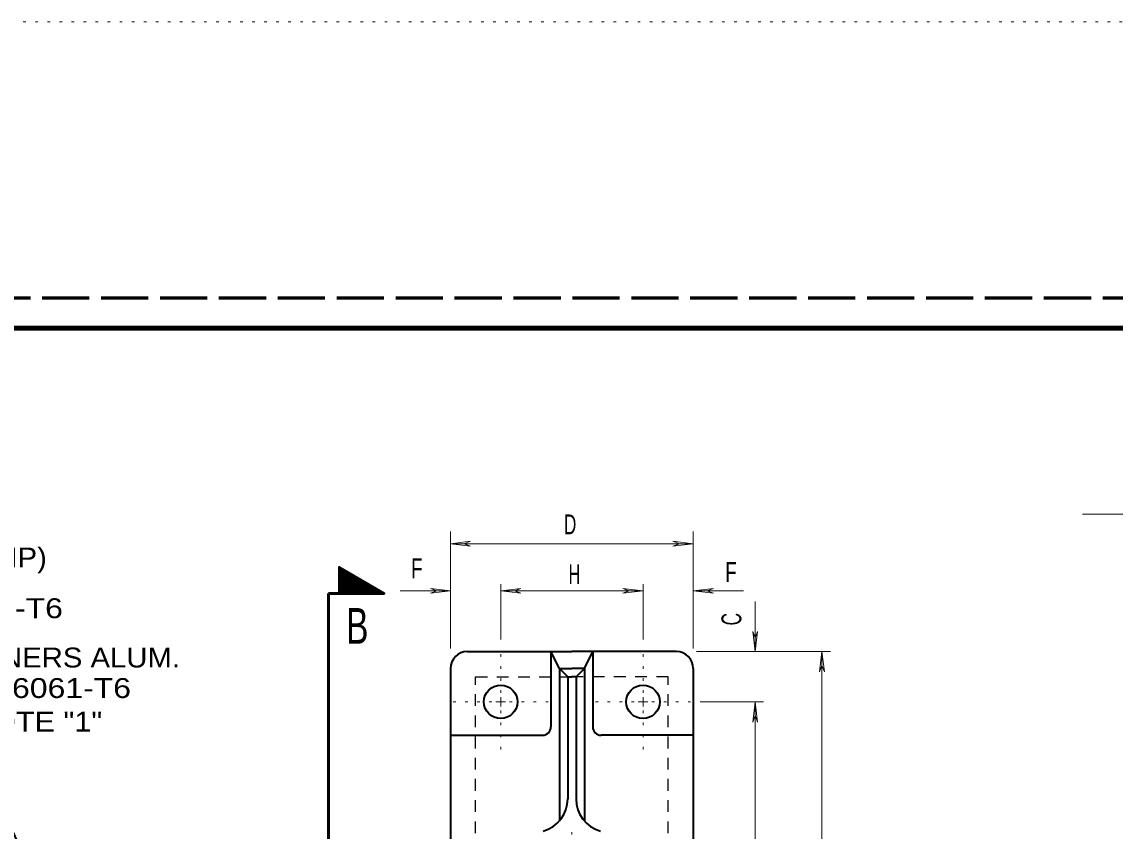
# Model space of a CAD drawing. Extents: x 312583 to 312854, y 144419 to 144597.
# Drawn here: x 312666.93 to 312708.67, y 144565.87 to 144596.78 of the extents above; entities that cross this region are included whole.
import ezdxf
from ezdxf.enums import TextEntityAlignment as Align

# ---------------------------------------------------------------- set-up
doc = ezdxf.new("R2010")
doc.units = 0
doc.header["$LTSCALE"] = 0.3
for name, pattern in [('DOTTED', [1.5, 0.3, -1.2]), ('LONG_DASH_SHORT_DASH', [9.9, 6, -1.2, 1.5, -1.2]), ('LONG_DASHED', [7.5, 6, -1.5]), ('SHORT_DASHED', [2.7, 1.5, -1.2])]:
    doc.linetypes.add(name, pattern=pattern)
for name, color, linetype, lineweight in [('1', 7, 'Continuous', 35), ('2', 7, 'Continuous', 13), ('62', 7, 'DOTTED', 13), ('63', 7, 'LONG_DASHED', 60)]:
    doc.layers.add(name, color=color, linetype=linetype, lineweight=lineweight)

msp = doc.modelspace()

# ---------------------------------------------------------------- linework, layer by layer
at = {"layer": '1', "linetype": 'LONG_DASH_SHORT_DASH', "lineweight": 13}
msp.add_line((312707.4292, 144577.9729), (312828.5012, 144577.9729), dxfattribs=at)
at = {"layer": '1'}
for p, q in [((312679.0537, 144575.9106), (312679.069, 144575.9259)), ((312679.0537, 144575.8723), (312679.0843, 144575.9183)), ((312679.0537, 144575.8263), (312679.0997, 144575.9029)), ((312679.0537, 144575.7803), (312679.1227, 144575.8953)), ((312679.0537, 144575.7343), (312679.138, 144575.8876)), ((312679.0537, 144575.7036), (312679.1533, 144575.8723)), ((312679.0537, 144575.6576), (312679.1763, 144575.8646)), ((312679.0537, 144575.6116), (312679.1917, 144575.8493)), ((312679.0537, 144575.5733), (312679.207, 144575.8416)), ((312679.0537, 144575.5349), (312679.2377, 144575.8339)), ((312679.0537, 144575.4813), (312679.253, 144575.8263)), ((312679.0537, 144575.4429), (312679.2683, 144575.8109)), ((312679.0537, 144575.4046), (312679.2913, 144575.8033)), ((312679.0537, 144575.3509), (312679.3067, 144575.7879)), ((312679.0537, 144575.3126), (312679.322, 144575.7803)), ((312679.0537, 144575.2743), (312679.3373, 144575.7726)), ((312679.0537, 144575.2283), (312679.3603, 144575.7573)), ((312679.0537, 144575.1823), (312679.3757, 144575.7496)), ((312679.0537, 144575.1439), (312679.391, 144575.7343)), ((312679.0537, 144575.1056), (312679.414, 144575.7189)), ((312679.0537, 144575.0519), (312679.437, 144575.7189)), ((312679.0537, 144575.0213), (312679.4447, 144575.7036)), ((312679.0537, 144574.9753), (312679.4753, 144575.6959)), ((312679.069, 144574.9523), (312679.4907, 144575.6806)), ((312679.092, 144574.9523), (312679.506, 144575.6729)), ((312679.1227, 144574.9523), (312679.529, 144575.6576)), ((312679.138, 144574.9523), (312679.5443, 144575.6576)), ((312679.1687, 144574.9523), (312679.5597, 144575.6423)), ((312679.1917, 144574.9599), (312679.5827, 144575.6346)), ((312679.2147, 144574.9599), (312679.598, 144575.6193)), ((312679.2377, 144574.9523), (312679.621, 144575.6116)), ((312679.2607, 144574.9523), (312679.6363, 144575.5963)), ((312679.2913, 144574.9523), (312679.6517, 144575.5886)), ((312679.3143, 144574.9523), (312679.6747, 144575.5809)), ((312679.3373, 144574.9523), (312679.69, 144575.5656)), ((312679.368, 144574.9523), (312679.713, 144575.5503)), ((312679.3833, 144574.9523), (312679.7283, 144575.5426)), ((312679.414, 144574.9599), (312679.7437, 144575.5349)), ((312679.437, 144574.9523), (312679.7667, 144575.5273)), ((312679.46, 144574.9523), (312679.782, 144575.5119)), ((312679.483, 144574.9523), (312679.805, 144575.5043)), ((312679.506, 144574.9523), (312679.8203, 144575.4889)), ((312679.5367, 144574.9523), (312679.8357, 144575.4813)), ((312679.5597, 144574.9523), (312679.8587, 144575.4736)), ((312679.5827, 144574.9523), (312679.874, 144575.4659)), ((312679.6133, 144574.9523), (312679.8893, 144575.4506)), ((312679.6287, 144574.9599), (312679.92, 144575.4429)), ((312679.6593, 144574.9523), (312679.9277, 144575.4276)), ((312679.6823, 144574.9523), (312679.9507, 144575.4123)), ((312679.7053, 144574.9523), (312679.9737, 144575.4123)), ((312679.736, 144574.9523), (312679.989, 144575.3969)), ((312679.7513, 144574.9523), (312680.0043, 144575.3893)), ((312679.782, 144574.9523), (312680.0273, 144575.3739)), ((312679.805, 144574.9523), (312680.0427, 144575.3663)), ((312679.828, 144574.9523), (312680.058, 144575.3509)), ((312679.8587, 144574.9523), (312680.081, 144575.3509)), ((312679.8817, 144574.9523), (312680.0963, 144575.3356)), ((312679.9047, 144574.9523), (312680.1117, 144575.3279)), ((312679.9277, 144574.9523), (312680.1347, 144575.3126)), ((312679.9507, 144574.9523), (312680.1577, 144575.3049)), ((312679.9813, 144574.9523), (312680.173, 144575.2896)), ((312680.0043, 144574.9523), (312680.1883, 144575.2819)), ((312680.0273, 144574.9523), (312680.2113, 144575.2743)), ((312680.0503, 144574.9523), (312680.2267, 144575.2589)), ((312680.0733, 144574.9523), (312680.242, 144575.2436)), ((312680.104, 144574.9523), (312680.265, 144575.2359)), ((312680.1193, 144574.9523), (312680.2803, 144575.2283)), ((312680.15, 144574.9523), (312680.2957, 144575.2206)), ((312680.173, 144574.9523), (312680.3187, 144575.2053)), ((312680.196, 144574.9523), (312680.334, 144575.1976)), ((312680.2267, 144574.9523), (312680.357, 144575.1823)), ((312680.242, 144574.9523), (312680.3723, 144575.1746)), ((312680.2727, 144574.9523), (312680.3953, 144575.1669)), ((312680.2957, 144574.9523), (312680.4183, 144575.1593)), ((312680.3187, 144574.9523), (312680.426, 144575.1439)), ((312680.3493, 144574.9523), (312680.449, 144575.1363)), ((312680.3647, 144574.9523), (312680.472, 144575.1209)), ((312680.3953, 144574.9523), (312680.4797, 144575.1056)), ((312680.4183, 144574.9523), (312680.5027, 144575.1056)), ((312680.449, 144574.9523), (312680.5257, 144575.0903)), ((312680.472, 144574.9523), (312680.541, 144575.0749)), ((312680.495, 144574.9523), (312680.5563, 144575.0673)), ((312680.518, 144574.9523), (312680.5793, 144575.0519)), ((312680.541, 144574.9523), (312680.6023, 144575.0443)), ((312680.564, 144574.9523), (312680.61, 144575.0366)), ((312680.5947, 144574.9523), (312680.633, 144575.0289)), ((312680.6177, 144574.9523), (312680.656, 144575.0136)), ((312680.6407, 144574.9523), (312680.6637, 144575.0059)), ((312680.6637, 144574.9523), (312680.6867, 144574.9906)), ((312680.6867, 144574.9523), (312680.7097, 144574.9829)), ((312680.7173, 144574.9523), (312680.725, 144574.9753)), ((312680.7403, 144574.9523), (312680.7403, 144574.9676))]:
    msp.add_line(p, q, dxfattribs=at)
at = {"layer": '1', "lineweight": 53}
for p in [(312678.632, 144572.8286), (312679.0537, 144574.9523)]:
    msp.add_line(p, (312678.632, 144574.9523), dxfattribs=at)
at = {"layer": '1', "lineweight": 40}
for p, q in [((312683.9297, 144572.7289), (312687.924, 144572.7289)), ((312687.1267, 144572.7289), (312687.1267, 144569.8539)), ((312687.4487, 144572.0849), (312687.1267, 144572.7289)), ((312691.9183, 144572.7289), (312687.924, 144572.7289)), ((312688.407, 144572.0849), (312688.729, 144572.7289)), ((312688.729, 144572.7289), (312688.729, 144569.8539)), ((312683.2933, 144572.0849), (312683.2933, 144559.3123)), ((312687.4487, 144572.0849), (312687.924, 144572.0849)), ((312687.4487, 144572.0849), (312687.4487, 144566.2506)), ((312687.7707, 144571.7629), (312687.7707, 144567.1016)), ((312688.407, 144572.0849), (312687.924, 144572.0849)), ((312688.085, 144571.7629), (312688.085, 144567.1016)), ((312688.407, 144572.0849), (312688.407, 144566.2506)), ((312692.5623, 144572.0849), (312692.5623, 144559.3123)), ((312683.2933, 144569.5319), (312686.8047, 144569.5319)), ((312692.5623, 144569.5319), (312689.0433, 144569.5319))]:
    msp.add_line(p, q, dxfattribs=at)
at = {"layer": '1', "lineweight": 158}
msp.add_lwpolyline([(312616.5, 144423.1446), (312616.5, 144585.0846), (312849, 144585.0846)], dxfattribs=at)
at = {"layer": '1', "lineweight": 53}
msp.add_lwpolyline([(312679.0537, 144574.9523), (312679.0537, 144575.9413), (312680.7557, 144574.9523)], close=True, dxfattribs=at)
msp.add_lwpolyline([(312687.924, 144559.3123), (312678.632, 144559.3123), (312678.632, 144572.8286)], dxfattribs=at)
at = {"layer": '1', "linetype": 'SHORT_DASHED', "lineweight": 25}
for points in [[(312684.2517, 144559.3123), (312684.2517, 144571.7706), (312687.924, 144571.7706)], [(312691.604, 144559.3123), (312691.604, 144571.7706), (312687.924, 144571.7706)]]:
    msp.add_lwpolyline(points, dxfattribs=at)
at = {"layer": '1', "lineweight": 40}
for points in [[(312687.4487, 144572.0849), (312687.7707, 144571.7629), (312687.924, 144571.7629)], [(312688.407, 144572.0849), (312688.085, 144571.7629), (312687.924, 144571.7629)]]:
    msp.add_lwpolyline(points, dxfattribs=at)
for centre in [(312685.21, 144570.8097), (312690.6431, 144570.8097)]:
    msp.add_circle(centre, 0.6389, dxfattribs=at)
for centre, radius, start, end in [((312683.9322, 144572.0875), 0.6389, 90, 180), ((312691.9209, 144572.0875), 0.6389, 0, 90), ((312686.8072, 144569.8514), 0.3194, 270, 0), ((312689.0459, 144569.8514), 0.3194, 180, 270), ((312686.4903, 144567.1025), 1.2778, 285.3355, 0), ((312689.3628, 144567.1025), 1.2778, 180, 254.6645)]:
    msp.add_arc(centre, radius, start, end, dxfattribs=at)
msp.add_spline([(312665.568, 144567.3086), (312666.166, 144566.5573), (312666.8407, 144565.1849), (312667.1013, 144563.3219), (312666.718, 144561.8193), (312666.2503, 144560.5313), (312665.637, 144559.2739), (312664.993, 144557.9859), (312664.5023, 144556.4909), (312664.303, 144555.5019), (312664.5253, 144553.3629), (312664.7937, 144552.1669), (312665.568, 144551.3389), (312666.373, 144551.7913), (312666.9557, 144553.2709), (312667.1013, 144555.3333), (312666.718, 144557.2883), (312666.373, 144558.1929), (312665.614, 144559.2203)], degree=3, dxfattribs=at)
at = {"layer": '2'}
for p, q in [((312683.2933, 144572.8516), (312683.2933, 144577.3213)), ((312692.5623, 144572.8516), (312692.5623, 144577.3213)), ((312683.2933, 144576.8459), (312684.06, 144576.9456)), ((312683.2933, 144576.8459), (312692.5623, 144576.8459)), ((312683.2933, 144576.8459), (312684.06, 144576.7539)), ((312684.06, 144576.9456), (312683.8147, 144576.8459)), ((312684.06, 144576.7539), (312683.8147, 144576.8459)), ((312691.788, 144576.9456), (312692.0333, 144576.8459)), ((312692.5623, 144576.8459), (312691.788, 144576.9456)), ((312691.788, 144576.7539), (312692.0333, 144576.8459)), ((312692.5623, 144576.8459), (312691.788, 144576.7539)), ((312682.5267, 144575.1439), (312682.772, 144575.0519)), ((312683.2933, 144575.0519), (312682.5267, 144575.1439)), ((312685.21, 144573.1889), (312685.21, 144575.3049)), ((312685.21, 144575.0519), (312685.9767, 144575.1439)), ((312685.9767, 144575.1439), (312685.7313, 144575.0519)), ((312689.8713, 144575.1439), (312690.1167, 144575.0519)), ((312690.6457, 144575.0519), (312689.8713, 144575.1439)), ((312690.6457, 144573.1889), (312690.6457, 144575.3049)), ((312692.5623, 144575.0519), (312693.329, 144575.1439)), ((312693.329, 144575.1439), (312693.0837, 144575.0519)), ((312683.2933, 144575.0519), (312681.3767, 144575.0519)), ((312682.5267, 144574.9599), (312682.772, 144575.0519)), ((312683.2933, 144575.0519), (312682.5267, 144574.9599)), ((312690.6457, 144575.0519), (312685.21, 144575.0519)), ((312685.21, 144575.0519), (312685.9767, 144574.9599)), ((312685.9767, 144574.9599), (312685.7313, 144575.0519)), ((312689.8713, 144574.9599), (312690.1167, 144575.0519)), ((312690.6457, 144575.0519), (312689.8713, 144574.9599)), ((312692.5623, 144575.0519), (312694.479, 144575.0519)), ((312692.5623, 144575.0519), (312693.329, 144574.9599)), ((312693.329, 144574.9599), (312693.0837, 144575.0519)), ((312694.9237, 144572.7289), (312694.9237, 144574.6456)), ((312694.8317, 144573.4956), (312694.9237, 144573.2503)), ((312694.9237, 144572.7289), (312694.8317, 144573.4956)), ((312695.0157, 144573.4956), (312694.9237, 144573.2503)), ((312694.9237, 144572.7289), (312695.0157, 144573.4956)), ((312697.7987, 144572.7289), (312692.685, 144572.7289)), ((312697.4767, 144572.7289), (312697.3847, 144571.9546)), ((312697.4767, 144559.3123), (312697.4767, 144572.7289)), ((312697.4767, 144572.7289), (312697.5763, 144571.9546)), ((312697.3847, 144571.9546), (312697.4767, 144572.1999)), ((312697.5763, 144571.9546), (312697.4767, 144572.1999)), ((312685.21, 144570.8123), (312685.21, 144570.9886)), ((312690.6457, 144570.8123), (312690.6457, 144570.9886)), ((312685.21, 144570.8123), (312685.026, 144570.8123)), ((312685.21, 144570.8123), (312685.394, 144570.8123)), ((312685.21, 144570.8123), (312685.21, 144570.6283)), ((312690.6457, 144570.8123), (312690.4617, 144570.8123)), ((312690.6457, 144570.8123), (312690.6457, 144570.6283)), ((312690.6457, 144570.8123), (312690.822, 144570.8123)), ((312695.2457, 144570.8123), (312692.8307, 144570.8123)), ((312694.9237, 144570.8123), (312694.8317, 144570.0379)), ((312694.9237, 144559.3123), (312694.9237, 144570.8123)), ((312694.9237, 144570.8123), (312695.0157, 144570.0379)), ((312694.8317, 144570.0379), (312694.9237, 144570.2833)), ((312695.0157, 144570.0379), (312694.9237, 144570.2833))]:
    msp.add_line(p, q, dxfattribs=at)
at = {"layer": '2', "linetype": 'DOTTED'}
for p, q in [((312685.21, 144571.1496), (312685.21, 144572.8976)), ((312690.6457, 144571.1496), (312690.6457, 144572.8976)), ((312684.8727, 144570.8123), (312683.1247, 144570.8123)), ((312685.21, 144570.4749), (312685.21, 144568.7193)), ((312685.5473, 144570.8123), (312687.2953, 144570.8123)), ((312690.3083, 144570.8123), (312688.5527, 144570.8123)), ((312690.6457, 144570.4749), (312690.6457, 144568.7193)), ((312690.983, 144570.8123), (312692.731, 144570.8123)), ((312687.924, 144562.5169), (312687.924, 144566.0666))]:
    msp.add_line(p, q, dxfattribs=at)
at = {"layer": '62'}
msp.add_line((312601.2, 144596.7846), (312853.5, 144596.7846), dxfattribs=at)
at = {"layer": '63'}
msp.add_line((312851.75, 144586.2246), (312583.526, 144586.2246), dxfattribs=at)

# ---------------------------------------------------------------- texts
at = {"layer": '1', "width": 0.7}
msp.add_text('B', height=1.365, dxfattribs=at).set_placement((312679.7321, 144573.0279), align=Align.CENTER)
at = {"layer": '2'}
for s, width, p in [('D', 0.65, (312687.621, 144577.2093)), ('SEE BOLT REQUIREMENTS (CAST CLAMP)', 1.1, (312644.8959, 144575.9414)), ('F', 0.7, (312681.7878, 144575.5309)), ('H', 0.6, (312687.8055, 144575.3078)), ('F', 0.7, (312693.7836, 144575.3876)), ('CAST CLAMP ASSY ALLOY 356-T6', 1.2, (312648.6323, 144574.0056)), ('STIFFENERS ALUM.', 1.1, (312662.279, 144572.1223)), ('ALLOY 6061-T6', 1.2, (312662.279, 144570.956)), ('SEE NOTE "1"', 1.15, (312662.279, 144569.674))]:
    msp.add_text(s, height=0.76, dxfattribs=dict(at, width=width)).set_placement(p)
at = {"layer": '2', "width": 0.65}
msp.add_text('C', height=0.76, rotation=90, dxfattribs=at).set_placement((312694.3978, 144573.7288))

doc.saveas('drawing.dxf')
